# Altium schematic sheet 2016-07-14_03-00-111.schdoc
size 359 x 162 mm; SheetNumber: 1; SheetTotal: 1
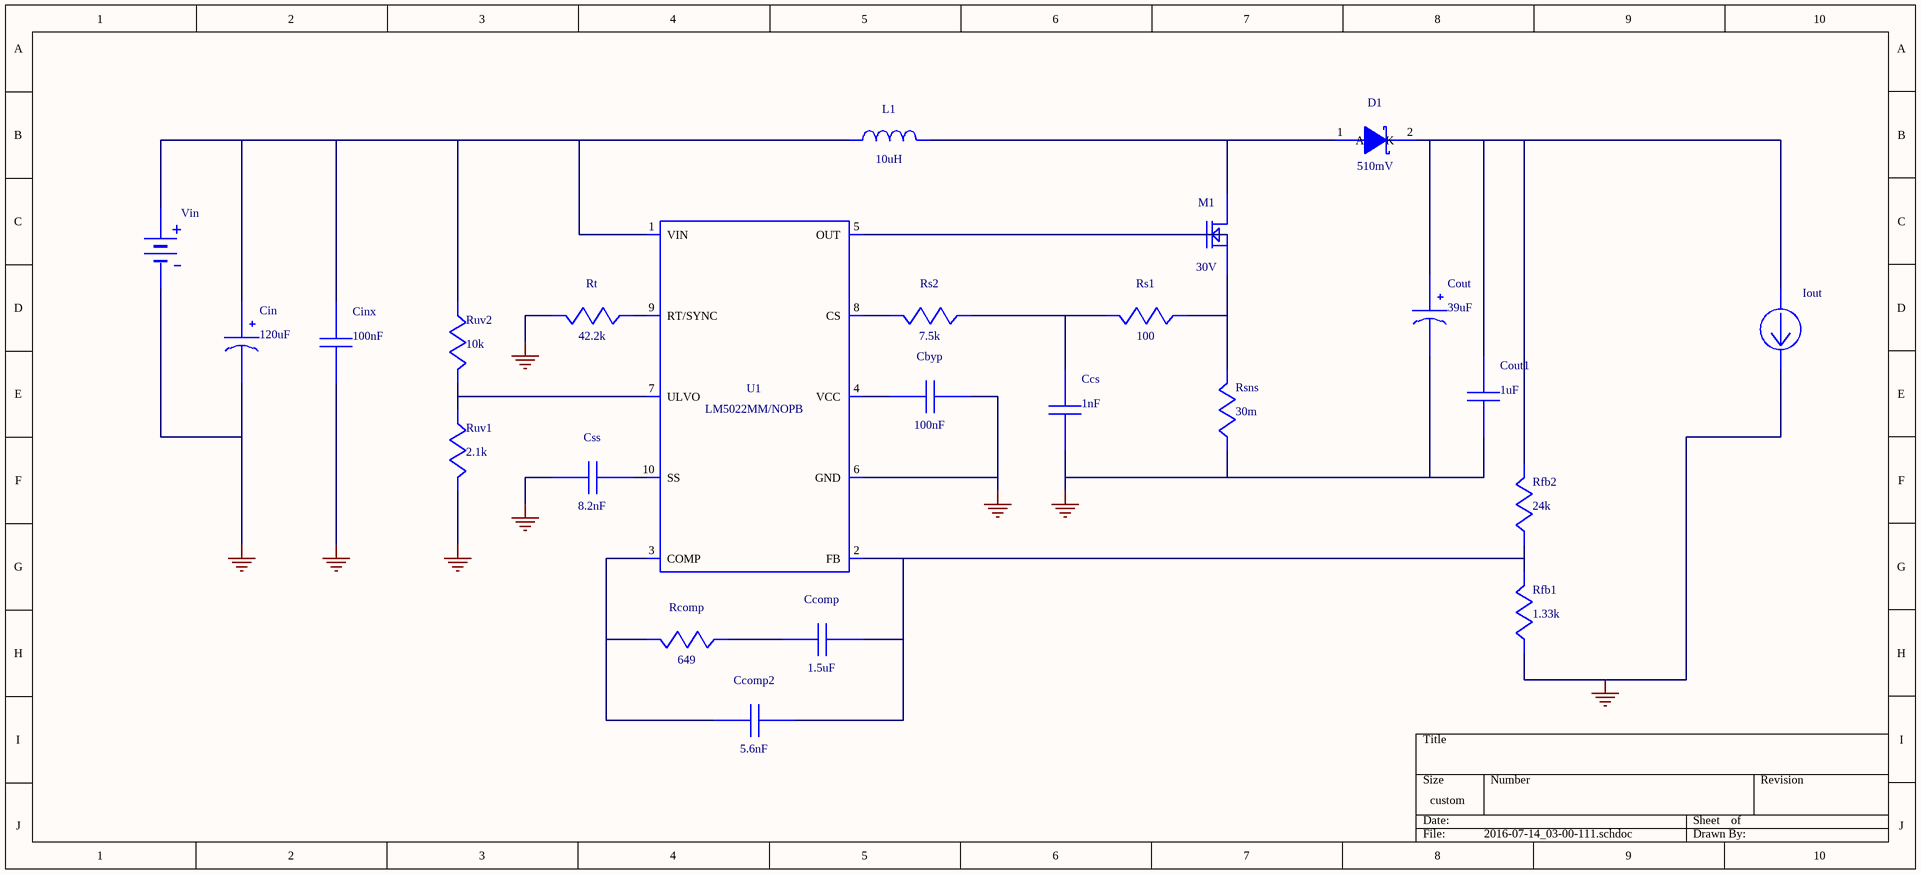
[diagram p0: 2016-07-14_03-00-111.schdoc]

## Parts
Cbyp  value 100nF  (hidden comment: 08053C104KAT2A)
Ccomp  value 1.5uF  (hidden comment: GRM21BR71E155KA88L)
Ccomp2  value 5.6nF  (hidden comment: CC0805KRX7R9BB562)
Ccs  value 1nF  (hidden comment: CL21C102JBCNFNC)
Cin  value 120uF  (hidden comment: 20SVPF120M)
Cinx  value 100nF  (hidden comment: GRM188R71C104KA01D)
Cout  value 39uF  (hidden comment: 35SVPF39M)
Cout1  value 1uF  (hidden comment: C1608X7R1H472K)
Css  value 8.2nF  (hidden comment: GRM155R71E822KA01D)
D1  value 510mV  (hidden comment: MBRD835LT4G)
Iout  WB_CURRENT_LOAD  (value not drawn)
L1  value 10uH  (hidden comment: SRP1270-100M)
M1  value 30V  (hidden comment: CSD17579Q3A)
Rcomp  value 649  (hidden comment: CRCW0402649RFKED)
Rfb1  value 1.33k  (hidden comment: CRCW04021K33FKED)
Rfb2  value 24k  (hidden comment: RC0603FR-0724KL)
Rs1  value 100  (hidden comment: CRCW0402100RFKED)
Rs2  value 7.5k  (hidden comment: CRCW04027K50FKED)
Rsns  value 30m  (hidden comment: CSRN2010FK30L0)
Rt  value 42.2k  (hidden comment: CRCW040242K2FKED)
Ruv1  value 2.1k  (hidden comment: CRCW04022K10FKED)
Ruv2  value 10k  (hidden comment: CRCW040210K0FKED)
U1  LM5022MM/NOPB
Vin  WB_BATTERY  (value not drawn)

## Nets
0: Cbyp.2 Ccs.2 Cin.2(-) Cinx.2 Cout.2(-) Cout1.2 Css.2 Iout.2(-) Rfb1.2 Rsns.2 Rt.1 Ruv1.1 U1.6(GND) Vin.2(-)
NetCbyp_1: Cbyp.1 U1.4(VCC)
NetCcomp2_2: Ccomp2.2 Rcomp.1 U1.3(COMP)
NetCcomp_1: Ccomp.1 Ccomp2.1 Rfb1.1 Rfb2.2 U1.2(FB)
NetCcomp_2: Ccomp.2 Rcomp.2
NetCcs_1: Ccs.1 Rs1.1 Rs2.2
NetCin_1: Cin.1(+) Cinx.1 L1.1 Ruv2.2 U1.1(VIN) Vin.1(+)
NetCout_1: Cout.1(+) Cout1.1 D1.2(K) Iout.1(+) Rfb2.1
NetCss_1: Css.1 U1.10(SS)
NetD1_1: D1.1(A) D1.3(A) L1.2 M1.5(Drain) M1.6(Drain) M1.7(Drain) M1.8(Drain) M1.9(Drain)
NetM1_1: M1.1(Source) M1.2(Source) M1.3(Source) Rs1.2 Rsns.1
NetM1_4: M1.4(Gate) U1.5(OUT)
NetRs2_1: Rs2.1 U1.8(CS)
NetRt_2: Rt.2 U1.9(RT/SYNC)
NetRuv1_2: Ruv1.2 Ruv2.1 U1.7(ULVO)

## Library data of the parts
Cbyp = 08053C104KAT2A: Manufacturer Name: AVX
Ccomp = GRM21BR71E155KA88L: GRM21BR71E155KA8; Manufacturer Name: MuRata
Ccomp2 = CC0805KRX7R9BB562: CC0805KRX7R9BB56; Manufacturer Name: Yageo America
Ccs = CL21C102JBCNFNC: Manufacturer Name: Samsung Electro-Mechanics
Cin = 20SVPF120M: Manufacturer Name: Panasonic
Cinx = GRM188R71C104KA01D: GRM188R71C104KA0; Manufacturer Name: MuRata
Cout = 35SVPF39M: Manufacturer Name: Panasonic
Cout1 = C1608X7R1H472K: C1608X7R1V105K08; Manufacturer Name: TDK
Css = GRM155R71E822KA01D: GRM155R71E822KA0; Manufacturer Name: MuRata
D1 = MBRD835LT4G: Manufacturer Name: ON Semiconductor
L1 = SRP1270-100M: Manufacturer Name: Bourns
M1 = CSD17579Q3A: Manufacturer Name: Texas Instruments
Rcomp = CRCW0402649RFKED: Manufacturer Name: Vishay-Dale
Rfb1 = CRCW04021K33FKED: Manufacturer Name: Vishay-Dale
Rfb2 = RC0603FR-0724KL: Manufacturer Name: Yageo America
Rs1 = CRCW0402100RFKED: Manufacturer Name: Vishay-Dale
Rs2 = CRCW04027K50FKED: Manufacturer Name: Vishay-Dale
Rsns = CSRN2010FK30L0: Manufacturer Name: Stackpole Electronics Inc
Rt = CRCW040242K2FKED: Manufacturer Name: Vishay-Dale
Ruv1 = CRCW04022K10FKED: Manufacturer Name: Vishay-Dale
Ruv2 = CRCW040210K0FKED: Manufacturer Name: Vishay-Dale
U1 = LM5022MM/NOPB: Manufacturer Name: Texas Instruments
